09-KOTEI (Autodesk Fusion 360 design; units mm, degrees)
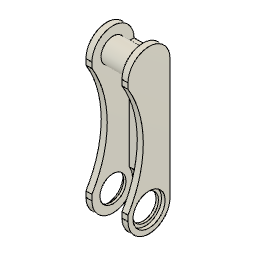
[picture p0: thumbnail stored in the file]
sketch "スケッチ1" plane through (0, 0, 0) normal (1, 0, 0) x axis (0, 0, -1)
  circle C1 centre (0, 40) radius 4
  point P1 (0, 0)
  point P2 (0, 40)
  vertical P1 P2
  dimension "d1" diameter C1 = 8
  dimension "d29" distance P1 P2 = 40
extrude "押し出し1" new body sketch "スケッチ1" + "スケッチ5" profile of S1:C1 distance 10
sketch "スケッチ2" plane through (5, 0, 0) normal (1, 0, 0) x axis (0, 0, -1)
  line L1 (-7, 0) -> (-7, 40)
  line L2 (7, 40) -> (7, 0)
  line L3 (0, 0) -> (0, 40)
  circle C1 centre (0, 40) radius 4
  arc A1 centre (0, 0) radius 7 clockwise from (7, 0) to (-7, 0)
  arc A2 centre (0, 40) radius 7 clockwise from (-7, 40) to (7, 40)
  point P7 (0, 40)
  point P9 (0, 40)
  point P8 (0, 0)
  tangent L1 A1
  tangent A1 L2
  parallel L1 L2
  tangent L2 A2
  tangent L1 A2
  vertical L3
  coincident P7 P9
  concentric C1 A2
  dimension "d4" radius A2 = 7
  dimension "d5" distance P7 P8 = 40
extrude "押し出し2" add sketch "スケッチ2" profile of C1 L1 A1 L2 A2 along normal blind 2
mirror "ミラー" sketch "スケッチ5" mirrorStitchTolerance 0.1
sketch "スケッチ3" plane through (0, 0, 0) normal (1, 0, 0) x axis (0, 0, -1)
  line L1 (7, 40) -> (5.4, 40)
  line L2 (7, 0) -> (7, 40)
  line L3 (5.4, 0) -> (7, 0)
  line L4 (5.4, 40) -> (5.4, 0)
  point P3 (7, 40)
  point P6 (7, 40)
  point P4 (7, 0)
  point P7 (7, 0)
  horizontal L1
  vertical L2
  horizontal L3
  vertical L4
  coincident P3 P6
  coincident P4 P7
  dimension "d10" distance L2 L4 = 1.6
extrude "押し出し3" add sketch "スケッチ3" distance 10
sketch "スケッチ4" plane through (0, 0, 0) normal (1, 0, 0) x axis (0, 0, -1)
  circle C1 centre (-36.9324, 20) radius 35
  arc A1 centre (0, 40) radius 7 clockwise from (-7, 40) to (7, 40)
  arc A2 centre (0, 0) radius 7 clockwise from (7, 0) to (-7, 0)
  tangent C1 A1
  tangent C1 A2
  dimension "d13" diameter C1 = 70
extrude "押し出し4" cut sketch "スケッチ4" profile of C1 no distance stored
sketch "スケッチ5" plane through (0, 0, 0) normal (1, 0, 0) x axis (0, 0, -1)
  circle C1 centre (0, 0) radius 6.5
  arc A1 centre (0, 0) radius 7 clockwise from (7, 0) to (-7, 0)
  concentric C1 A1
  dimension "d15" diameter C1 = 13
extrude "押し出し5" cut sketch "スケッチ5" profile of C1 distance 10
chamfer "面取り" distance 0.2
hole "穴1" HoleDepth 2 HoleDiameter 8.7 TipAngle 118 CBDepth 1.2 CBDiameter 10.7
hole "穴2" HoleDepth 2 HoleDiameter 8.7 TipAngle 118 CBDepth 1.2 CBDiameter 10.7
joint_origin "JointOrigin2" OffsetX 0 OffsetY 0 OffsetZ 0 AngleZ 0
